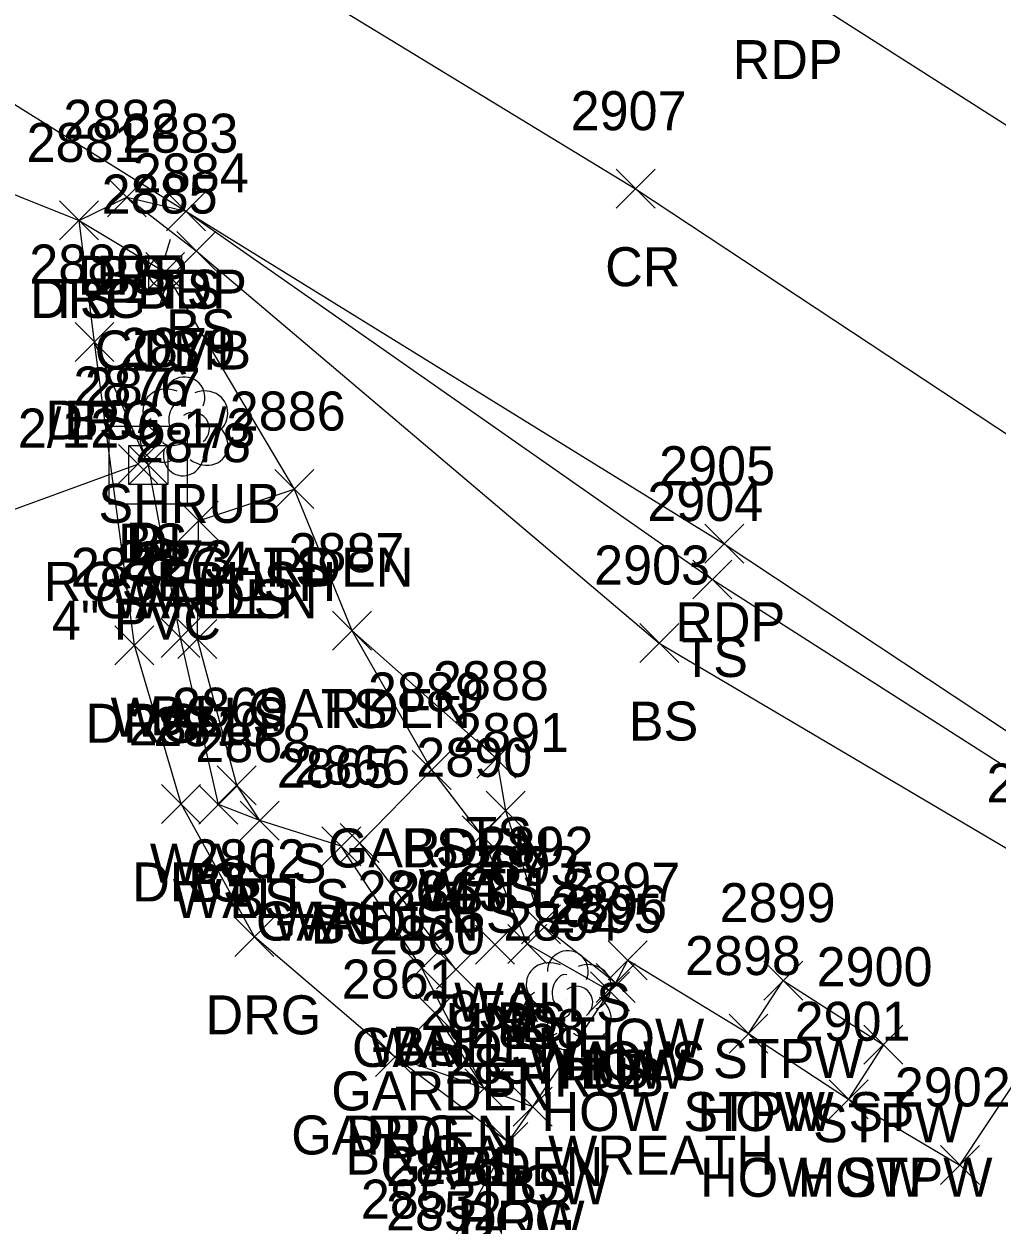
# Model space of a CAD drawing. Extents: x 1499292 to 1501024, y 534584 to 538043.
# Drawn here: x 1499668.2 to 1499718.2, y 537733.8 to 537795.2 of the extents above; entities that cross this region are included whole.
import ezdxf

# ---------------------------------------------------------------- set-up
doc = ezdxf.new("R2010")
doc.units = 0
for name, color, linetype in [('D_A', 7, 'Continuous'), ('D_C', 7, 'Continuous'), ('D_I', 7, 'Continuous'), ('D_TIC', 7, 'Continuous'), ('DCP', 7, 'Continuous'), ('DS', 7, 'Continuous'), ('L_A', 7, 'Continuous'), ('L_C', 7, 'Continuous'), ('L_I', 7, 'Continuous'), ('L_TIC', 7, 'Continuous'), ('LAPB', 7, 'Continuous'), ('LBC', 7, 'Continuous'), ('LBF', 7, 'Continuous'), ('LELB', 7, 'Continuous'), ('LSH', 7, 'Continuous'), ('LWS', 7, 'Continuous'), ('P_A', 7, 'Continuous'), ('P_I', 7, 'Continuous'), ('P_TIC', 7, 'Continuous'), ('PET', 7, 'Continuous'), ('PRC', 7, 'Continuous'), ('R_A', 7, 'Continuous'), ('R_I', 7, 'Continuous'), ('R_TIC', 7, 'Continuous'), ('RDG', 7, 'Continuous'), ('RDP', 7, 'Continuous'), ('U_A', 7, 'Continuous'), ('U_C', 7, 'Continuous'), ('U_I', 7, 'Continuous'), ('UP', 7, 'Continuous')]:
    doc.layers.add(name, color=color, linetype=linetype)

msp = doc.modelspace()

# ---------------------------------------------------------------- linework, layer by layer
at = {"layer": 'D_TIC'}
for points in [[(1499673.076, 537771.661), (1499675.076, 537773.661)], [(1499675.076, 537771.661), (1499673.076, 537773.661)], [(1499691.393, 537747.018), (1499693.393, 537749.018)], [(1499693.393, 537747.018), (1499691.393, 537749.018)]]:
    msp.add_lwpolyline(points, dxfattribs=at)
at = {"layer": 'DCP'}
msp.add_lwpolyline([(1499658.416, 537766.949), (1499674.076, 537772.661)], dxfattribs=at)
at = {"layer": 'DS'}
for p, q in [((1499672.605, 537774.607), (1499676.605, 537774.607)), ((1499672.605, 537770.607), (1499672.605, 537774.607)), ((1499676.605, 537774.607), (1499676.605, 537770.607)), ((1499673.605, 537771.607), (1499673.605, 537773.607)), ((1499673.605, 537773.607), (1499675.605, 537773.607)), ((1499675.605, 537773.607), (1499675.605, 537771.607)), ((1499674.61, 537772.609), (1499674.61, 537772.609)), ((1499674.61, 537772.609), (1499674.61, 537772.609)), ((1499675.605, 537771.607), (1499673.605, 537771.607)), ((1499676.605, 537770.607), (1499672.605, 537770.607))]:
    msp.add_line(p, q, dxfattribs=at)
at = {"layer": 'L_TIC'}
for points in [[(1499672.505, 537785.342), (1499674.505, 537787.342)], [(1499674.505, 537785.342), (1499672.505, 537787.342)], [(1499675.536, 537784.628), (1499677.536, 537786.628)], [(1499677.536, 537784.628), (1499675.536, 537786.628)], [(1499670.052, 537784.153), (1499672.052, 537786.153)], [(1499672.052, 537784.153), (1499670.052, 537786.153)], [(1499676.07, 537782.592), (1499678.07, 537784.592)], [(1499678.07, 537782.592), (1499676.07, 537784.592)], [(1499674.472, 537781.508), (1499676.472, 537783.508)], [(1499676.472, 537781.508), (1499674.472, 537783.508)], [(1499670.846, 537777.917), (1499672.846, 537779.917)], [(1499672.846, 537777.917), (1499670.846, 537779.917)], [(1499673.61, 537771.609), (1499675.61, 537773.609)], [(1499675.61, 537771.609), (1499673.61, 537773.609)], [(1499681.099, 537770.379), (1499683.099, 537772.379)], [(1499683.099, 537770.379), (1499681.099, 537772.379)], [(1499681.099, 537770.379), (1499683.099, 537772.379)], [(1499683.099, 537770.379), (1499681.099, 537772.379)], [(1499676.189, 537768.757), (1499678.189, 537770.757)], [(1499678.189, 537768.757), (1499676.189, 537770.757)], [(1499676.189, 537768.757), (1499678.189, 537770.757)], [(1499678.189, 537768.757), (1499676.189, 537770.757)], [(1499702.551, 537765.74), (1499704.551, 537767.74)], [(1499704.551, 537765.74), (1499702.551, 537767.74)], [(1499684.056, 537763.119), (1499686.056, 537765.119)], [(1499686.056, 537763.119), (1499684.056, 537765.119)], [(1499684.056, 537763.119), (1499686.056, 537765.119)], [(1499686.056, 537763.119), (1499684.056, 537765.119)], [(1499675.259, 537762.746), (1499677.259, 537764.746)], [(1499677.259, 537762.746), (1499675.259, 537764.746)], [(1499676.126, 537762.686), (1499678.126, 537764.686)], [(1499678.126, 537762.686), (1499676.126, 537764.686)], [(1499699.821, 537762.481), (1499701.821, 537764.481)], [(1499701.821, 537762.481), (1499699.821, 537764.481)], [(1499691.471, 537756.552), (1499693.471, 537758.552)], [(1499693.471, 537756.552), (1499691.471, 537758.552)], [(1499688.144, 537755.971), (1499690.144, 537757.971)], [(1499690.144, 537755.971), (1499688.144, 537757.971)], [(1499688.144, 537755.971), (1499690.144, 537757.971)], [(1499690.144, 537755.971), (1499688.144, 537757.971)], [(1499688.144, 537755.971), (1499690.144, 537757.971)], [(1499690.144, 537755.971), (1499688.144, 537757.971)], [(1499678.143, 537755.19), (1499680.143, 537757.19)], [(1499680.143, 537755.19), (1499678.143, 537757.19)], [(1499677.208, 537754.193), (1499679.208, 537756.193)], [(1499679.208, 537754.193), (1499677.208, 537756.193)], [(1499691.938, 537753.891), (1499693.938, 537755.891)], [(1499693.938, 537753.891), (1499691.938, 537755.891)], [(1499691.938, 537753.891), (1499693.938, 537755.891)], [(1499693.938, 537753.891), (1499691.938, 537755.891)], [(1499679.323, 537753.372), (1499681.323, 537755.372)], [(1499681.323, 537753.372), (1499679.323, 537755.372)], [(1499679.323, 537753.372), (1499681.323, 537755.372)], [(1499681.323, 537753.372), (1499679.323, 537755.372)], [(1499690.705, 537752.622), (1499692.705, 537754.622)], [(1499692.705, 537752.622), (1499690.705, 537754.622)], [(1499683.508, 537752.062), (1499685.508, 537754.062)], [(1499685.508, 537752.062), (1499683.508, 537754.062)], [(1499684.457, 537752.222), (1499686.457, 537754.222)], [(1499686.457, 537752.222), (1499684.457, 537754.222)], [(1499684.457, 537752.222), (1499686.457, 537754.222)], [(1499686.457, 537752.222), (1499684.457, 537754.222)], [(1499693.76, 537748.06), (1499695.76, 537750.06)], [(1499695.76, 537748.06), (1499693.76, 537750.06)], [(1499693.048, 537747.054), (1499695.048, 537749.054)], [(1499695.048, 537747.054), (1499693.048, 537749.054)], [(1499698.211, 537746.217), (1499700.211, 537748.217)], [(1499700.211, 537746.217), (1499698.211, 537748.217)], [(1499687.651, 537745.809), (1499689.651, 537747.809)], [(1499689.651, 537745.809), (1499687.651, 537747.809)], [(1499689.388, 537745.741), (1499691.388, 537747.741)], [(1499691.388, 537745.741), (1499689.388, 537747.741)], [(1499689.388, 537745.741), (1499691.388, 537747.741)], [(1499691.388, 537745.741), (1499689.388, 537747.741)], [(1499697.593, 537745.054), (1499699.593, 537747.054)], [(1499699.593, 537745.054), (1499697.593, 537747.054)], [(1499697.593, 537745.054), (1499699.593, 537747.054)], [(1499699.593, 537745.054), (1499697.593, 537747.054)], [(1499706.188, 537745.17), (1499708.188, 537747.17)], [(1499708.188, 537745.17), (1499706.188, 537747.17)], [(1499697.305, 537744.626), (1499699.305, 537746.626)], [(1499699.305, 537744.626), (1499697.305, 537746.626)], [(1499697.305, 537744.626), (1499699.305, 537746.626)], [(1499699.305, 537744.626), (1499697.305, 537746.626)], [(1499688.325, 537743.511), (1499690.325, 537745.511)], [(1499690.325, 537743.511), (1499688.325, 537745.511)], [(1499704.404, 537742.454), (1499706.404, 537744.454)], [(1499706.404, 537742.454), (1499704.404, 537744.454)], [(1499704.404, 537742.454), (1499706.404, 537744.454)], [(1499706.404, 537742.454), (1499704.404, 537744.454)], [(1499711.324, 537741.883), (1499713.324, 537743.883)], [(1499713.324, 537741.883), (1499711.324, 537743.883)], [(1499686.27, 537741.251), (1499688.27, 537743.251)], [(1499688.27, 537741.251), (1499686.27, 537743.251)], [(1499690.846, 537739.643), (1499692.846, 537741.643)], [(1499692.846, 537739.643), (1499690.846, 537741.643)], [(1499690.846, 537739.643), (1499692.846, 537741.643)], [(1499692.846, 537739.643), (1499690.846, 537741.643)], [(1499690.846, 537739.643), (1499692.846, 537741.643)], [(1499692.846, 537739.643), (1499690.846, 537741.643)], [(1499709.54, 537739.083), (1499711.54, 537741.083)], [(1499711.54, 537739.083), (1499709.54, 537741.083)], [(1499709.54, 537739.083), (1499711.54, 537741.083)], [(1499711.54, 537739.083), (1499709.54, 537741.083)], [(1499693.333, 537738.703), (1499695.333, 537740.703)], [(1499695.333, 537738.703), (1499693.333, 537740.703)], [(1499693.333, 537738.703), (1499695.333, 537740.703)], [(1499695.333, 537738.703), (1499693.333, 537740.703)], [(1499692.073, 537736.884), (1499694.073, 537738.884)], [(1499694.073, 537736.884), (1499692.073, 537738.884)], [(1499715.249, 537735.711), (1499717.249, 537737.711)], [(1499717.249, 537735.711), (1499715.249, 537737.711)]]:
    msp.add_lwpolyline(points, dxfattribs=at)
at = {"layer": 'LAPB'}
for points in [[(1499677.189, 537769.757), (1499682.099, 537771.379), (1499685.056, 537764.119), (1499689.144, 537756.971)], [(1499685.457, 537753.222), (1499689.144, 537756.971)], [(1499691.846, 537740.643), (1499689.325, 537744.511)], [(1499691.846, 537740.643), (1499687.27, 537742.251)]]:
    msp.add_lwpolyline(points, dxfattribs=at)
at = {"layer": 'LBC'}
msp.add_lwpolyline([(1499697.587, 537727.89), (1499690.115, 537732.638), (1499693.073, 537737.884), (1499694.333, 537739.703), (1499698.305, 537745.626), (1499698.593, 537746.054), (1499699.211, 537747.217), (1499705.404, 537743.454), (1499710.54, 537740.083), (1499716.249, 537736.711), (1499721.755, 537744.999), (1499738.986, 537733.643), (1499732.104, 537722.822), (1499729.121, 537718.079), (1499724.689, 537711.282), (1499721.272, 537713.245)], dxfattribs=at)
at = {"layer": 'LBF'}
msp.add_lwpolyline([(1499705.404, 537743.454), (1499707.188, 537746.17), (1499712.324, 537742.883), (1499710.54, 537740.083)], dxfattribs=at)
at = {"layer": 'LELB'}
for points in [[(1499673.505, 537786.342), (1499677.07, 537783.592), (1499700.821, 537763.481), (1499719.743, 537752.304), (1499723.657, 537747.33), (1499740.89, 537735.965), (1499752.712, 537719.821), (1499760.138, 537714.193), (1499776.543, 537702.52), (1499783.898, 537695.878)], [(1499671.052, 537785.153), (1499675.472, 537782.508), (1499682.099, 537771.379)], [(1499676.536, 537785.628), (1499703.551, 537766.74), (1499721.632, 537755.195), (1499743.729, 537738.33)], [(1499694.333, 537739.703), (1499691.846, 537740.643), (1499688.651, 537746.809), (1499684.508, 537753.062), (1499680.323, 537754.372), (1499678.208, 537755.193), (1499676.259, 537763.746), (1499674.61, 537772.609), (1499671.846, 537778.917)], [(1499685.056, 537764.119), (1499692.471, 537757.552), (1499692.938, 537754.891)], [(1499689.144, 537756.971), (1499691.705, 537753.622), (1499694.048, 537748.054), (1499698.305, 537745.626)]]:
    msp.add_lwpolyline(points, dxfattribs=at)
at = {"layer": 'LSH'}
for p, q in [((1499676.416, 537774.644), (1499676.416, 537774.644)), ((1499676.416, 537774.644), (1499676.416, 537774.644)), ((1499696.087, 537745.221), (1499696.087, 537745.221)), ((1499696.087, 537745.221), (1499696.087, 537745.221))]:
    msp.add_line(p, q, dxfattribs=at)
for centre in [(1499676.463, 537776.078), (1499696.134, 537746.655)]:
    msp.add_arc(centre, 1.047, 335.52715, 180.95627, dxfattribs=at)
for centre, major_axis, ratio, start_param, end_param in [((1499675.624, 537775.31), (1.21, -0.512), 0.895232, 1.570796, 4.712389), ((1499677.458, 537775.227), (-1.141, -0.483), 0.949671, 1.570796, 4.712389), ((1499676.208, 537775.102), (-0.208, -0.792), 0.645439, 3.141593, 6.283185), ((1499676.916, 537774.477), (-0.5, 0.667), 0.989748, 3.141593, 6.283185), ((1499675.333, 537773.935), (0.584, -1.042), 0.959034, 3.141593, 6.283185), ((1499677.416, 537773.811), (-1.09, 0.792), 0.841452, 1.570796, 4.712389), ((1499676.416, 537773.144), (0.265, 1.061), 0.942809, 1.570796, 4.712389), ((1499675.958, 537773.894), (-0.625, -0.083), 0.423636, 0, 3.141593), ((1499695.295, 537745.887), (1.21, -0.512), 0.895232, 1.570796, 4.712389), ((1499697.129, 537745.804), (-1.141, -0.483), 0.949671, 1.570796, 4.712389), ((1499695.879, 537745.679), (-0.208, -0.792), 0.645439, 3.141593, 6.283185), ((1499696.587, 537745.054), (-0.5, 0.667), 0.989748, 3.141593, 6.283185), ((1499695.004, 537744.512), (0.584, -1.042), 0.959034, 3.141593, 6.283185), ((1499697.087, 537744.388), (-1.09, 0.792), 0.841452, 1.570796, 4.712389), ((1499695.629, 537744.471), (-0.625, -0.083), 0.423636, 0, 3.141593), ((1499696.087, 537743.721), (0.265, 1.061), 0.942809, 1.570796, 4.712389)]:
    msp.add_ellipse(centre, major_axis=major_axis, ratio=ratio, start_param=start_param, end_param=end_param, dxfattribs=at)
at = {"layer": 'LWS'}
for points in [[(1499680.323, 537754.372), (1499679.143, 537756.19), (1499677.126, 537763.686), (1499677.189, 537769.757)], [(1499692.938, 537754.891), (1499694.76, 537749.06), (1499698.593, 537746.054)], [(1499690.388, 537746.741), (1499685.457, 537753.222)]]:
    msp.add_lwpolyline(points, dxfattribs=at)
at = {"layer": 'P_TIC'}
for points in [[(1499698.614, 537785.782), (1499700.614, 537787.782)], [(1499700.614, 537785.782), (1499698.614, 537787.782)], [(1499675.536, 537784.628), (1499677.536, 537786.628)], [(1499677.536, 537784.628), (1499675.536, 537786.628)], [(1499703.158, 537767.574), (1499705.158, 537769.574)], [(1499705.158, 537767.574), (1499703.158, 537769.574)]]:
    msp.add_lwpolyline(points, dxfattribs=at)
at = {"layer": 'PET'}
for points in [[(1499318.777, 538007.185), (1499356.077, 537991.329), (1499396.207, 537971.039), (1499437.012, 537950.167), (1499476.074, 537929.172), (1499509.306, 537910.677), (1499546.423, 537890.59), (1499566.293, 537879.272), (1499602.082, 537858.76), (1499615.195, 537851.418), (1499643.027, 537835.063), (1499676.234, 537815.623), (1499707.101, 537797.403), (1499725.198, 537785.865), (1499749.466, 537768.587), (1499768.247, 537754.161), (1499782.48, 537740.777), (1499805.279, 537716.472), (1499820.533, 537699.08)], [(1499310.023, 537983.746), (1499343.075, 537969.541), (1499383.731, 537949.439), (1499427.71, 537927.425), (1499464.171, 537907.983), (1499500.199, 537887.497), (1499544.495, 537863.142), (1499587.74, 537838.677), (1499616.247, 537822.183), (1499651.021, 537801.554), (1499676.536, 537785.628), (1499704.158, 537768.574), (1499722.55, 537756.398), (1499745.414, 537739.8), (1499767.298, 537722.36), (1499790.892, 537701.646), (1499806.057, 537686.036), (1499813.912, 537693.068), (1499820.533, 537699.08)]]:
    msp.add_lwpolyline(points, dxfattribs=at)
at = {"layer": 'PRC'}
msp.add_lwpolyline([(1499314.647, 537995.238), (1499351.896, 537980.059), (1499390.853, 537960.785), (1499432.771, 537938.063), (1499470.255, 537918.917), (1499503.529, 537899.736), (1499550.301, 537873.589), (1499594.281, 537849.334), (1499631.071, 537828.01), (1499665.93, 537807.267), (1499699.614, 537786.782), (1499728.317, 537767.815), (1499774.937, 537731.181), (1499796.918, 537710.716), (1499813.912, 537693.068)], dxfattribs=at)
at = {"layer": 'R_TIC'}
for points in [[(1499672.505, 537785.342), (1499674.505, 537787.342)], [(1499674.505, 537785.342), (1499672.505, 537787.342)], [(1499675.536, 537784.628), (1499677.536, 537786.628)], [(1499677.536, 537784.628), (1499675.536, 537786.628)], [(1499670.052, 537784.153), (1499672.052, 537786.153)], [(1499672.052, 537784.153), (1499670.052, 537786.153)], [(1499670.052, 537784.153), (1499672.052, 537786.153)], [(1499672.052, 537784.153), (1499670.052, 537786.153)], [(1499670.846, 537777.917), (1499672.846, 537779.917)], [(1499672.846, 537777.917), (1499670.846, 537779.917)], [(1499672.894, 537762.367), (1499674.894, 537764.367)], [(1499674.894, 537762.367), (1499672.894, 537764.367)], [(1499675.292, 537754.227), (1499677.292, 537756.227)], [(1499677.292, 537754.227), (1499675.292, 537756.227)], [(1499679.055, 537747.413), (1499681.055, 537749.413)], [(1499681.055, 537747.413), (1499679.055, 537749.413)], [(1499686.27, 537741.251), (1499688.27, 537743.251)], [(1499688.27, 537741.251), (1499686.27, 537743.251)], [(1499692.073, 537736.884), (1499694.073, 537738.884)], [(1499694.073, 537736.884), (1499692.073, 537738.884)]]:
    msp.add_lwpolyline(points, dxfattribs=at)
at = {"layer": 'RDG'}
msp.add_lwpolyline([(1499693.073, 537737.884), (1499687.27, 537742.251), (1499680.055, 537748.413), (1499676.292, 537755.227), (1499673.894, 537763.367), (1499671.846, 537778.917), (1499671.052, 537785.153)], dxfattribs=at)
at = {"layer": 'RDP'}
msp.add_lwpolyline([(1499651.021, 537801.554), (1499653.673, 537795.813), (1499661.704, 537788.897), (1499671.052, 537785.153), (1499673.505, 537786.342), (1499676.536, 537785.628)], dxfattribs=at)
at = {"layer": 'UP'}
for p, q in [((1499675.722, 537784.175), (1499675.472, 537783.341)), ((1499674.639, 537781.675), (1499674.639, 537783.341)), ((1499674.639, 537783.341), (1499676.306, 537783.341)), ((1499676.306, 537783.341), (1499676.306, 537781.675)), ((1499675.472, 537782.508), (1499675.472, 537782.508)), ((1499676.306, 537781.675), (1499674.639, 537781.675)), ((1499675.222, 537780.841), (1499675.472, 537781.675))]:
    msp.add_line(p, q, dxfattribs=at)
msp.add_circle((1499675.472, 537782.508), 0.833, dxfattribs=at)

# ---------------------------------------------------------------- texts
at = {"layer": 'D_A'}
for s, p in [('P', (1499673.453, 537767.661)), ('DI', (1499673.665, 537767.609)), ('UND', (1499689.865, 537743.018))]:
    msp.add_text(s, height=2, dxfattribs=at).set_placement(p)
at = {"layer": 'D_C'}
msp.add_text('4" PVC', height=2, dxfattribs=at).set_placement((1499669.658, 537763.661))
at = {"layer": 'D_I'}
for s, p in [('2876', (1499670.761, 537775.661)), ('2877', (1499671.35, 537775.609)), ('2867', (1499689.086, 537751.018))]:
    msp.add_text(s, height=2, dxfattribs=at).set_placement(p)
at = {"layer": 'L_A'}
for s, p in [('BS', (1499671.946, 537781.342)), ('TS', (1499674.946, 537780.628)), ('TS', (1499669.461, 537780.153)), ('BS', (1499675.511, 537778.592)), ('TS', (1499673.882, 537777.508)), ('BS', (1499670.287, 537773.917)), ('SHRUB', (1499672.046, 537769.644)), ('BS', (1499673.051, 537767.609)), ('GARDEN', (1499676.769, 537766.379)), ('TS', (1499680.509, 537766.379)), ('GARDEN', (1499671.858, 537764.757)), ('WALLS', (1499672.732, 537764.757)), ('TS', (1499701.961, 537761.74)), ('GARDEN', (1499679.725, 537759.119)), ('TS', (1499683.465, 537759.119)), ('WALLS', (1499672.67, 537758.686)), ('BS', (1499674.7, 537758.746)), ('BS', (1499699.262, 537758.481)), ('TS', (1499690.88, 537752.552)), ('GARDEN', (1499683.813, 537751.971)), ('GARDEN', (1499683.813, 537751.971)), ('BS', (1499687.585, 537751.971)), ('WALLS', (1499674.686, 537751.19)), ('BS', (1499676.649, 537750.193)), ('WALLS', (1499688.482, 537749.891)), ('TS', (1499691.348, 537749.891)), ('WALLS', (1499675.866, 537749.372)), ('BS', (1499678.764, 537749.372)), ('GARDEN', (1499680.126, 537748.222)), ('WALLS', (1499681, 537748.222)), ('BS', (1499682.949, 537748.062)), ('BS', (1499690.146, 537748.622)), ('WALLS', (1499690.304, 537744.06)), ('BS', (1499692.489, 537743.054)), ('HOW', (1499696.597, 537742.217)), ('GARDEN', (1499685.058, 537741.741)), ('WALLS', (1499685.932, 537741.741)), ('BS', (1499687.092, 537741.809)), ('WALLS', (1499694.137, 537741.054)), ('HOW', (1499695.979, 537741.054)), ('STPW', (1499703.582, 537741.17)), ('SHRUB', (1499691.717, 537740.221)), ('HOW', (1499695.691, 537740.626)), ('BS', (1499696.746, 537740.626)), ('GARDEN', (1499683.995, 537739.511)), ('HOW STPW ST', (1499694.782, 537738.454)), ('HOW', (1499702.79, 537738.454)), ('STPW', (1499708.718, 537737.883)), ('GARDEN', (1499681.939, 537737.251)), ('GARDEN', (1499686.515, 537735.643)), ('GARDEN', (1499686.515, 537735.643)), ('BS', (1499690.287, 537735.643)), ('HOW', (1499691.719, 537734.703)), ('BS', (1499692.774, 537734.703)), ('HOW STPW', (1499702.918, 537735.083)), ('HOW', (1499707.926, 537735.083)), ('HOW', (1499690.459, 537732.884))]:
    msp.add_text(s, height=2, dxfattribs=at).set_placement(p)
at = {"layer": 'L_C'}
for s, p in [('ROSEBUSH', (1499669.235, 537765.644)), ('BRIDAL WREATH', (1499684.717, 537736.221))]:
    msp.add_text(s, height=2, dxfattribs=at).set_placement(p)
at = {"layer": 'L_I'}
for s, p in [('2882', (1499670.245, 537789.342)), ('2883', (1499673.276, 537788.628)), ('2881', (1499668.359, 537788.153)), ('2884', (1499673.811, 537786.592)), ('2885', (1499672.213, 537785.508)), ('2880', (1499668.5, 537781.917)), ('2879', (1499673.148, 537777.644)), ('2877', (1499671.35, 537775.609)), ('2886', (1499678.785, 537774.379)), ('2886', (1499678.785, 537774.379)), ('2878', (1499673.929, 537772.757)), ('2878', (1499673.929, 537772.757)), ('2904', (1499700.213, 537769.74)), ('2887', (1499681.796, 537767.119)), ('2887', (1499681.796, 537767.119)), ('2873', (1499672.999, 537766.746)), ('2874', (1499673.866, 537766.686)), ('2903', (1499697.483, 537766.481)), ('2888', (1499689.211, 537760.552)), ('2889', (1499685.876, 537759.971)), ('2889', (1499685.876, 537759.971)), ('2889', (1499685.876, 537759.971)), ('2869', (1499675.828, 537759.19)), ('2870', (1499674.861, 537758.193)), ('2891', (1499690.245, 537757.891)), ('2891', (1499690.245, 537757.891)), ('2868', (1499677.016, 537757.372)), ('2868', (1499677.016, 537757.372)), ('2890', (1499688.358, 537756.622)), ('2865', (1499681.201, 537756.062)), ('2866', (1499682.094, 537756.222)), ('2866', (1499682.094, 537756.222)), ('2911', (1499717.617, 537755.304)), ('2892', (1499691.5, 537752.06)), ('2893', (1499690.788, 537751.054)), ('2897', (1499695.951, 537750.217)), ('2864', (1499685.344, 537749.809)), ('2863', (1499687.081, 537749.741)), ('2863', (1499687.081, 537749.741)), ('2896', (1499695.278, 537749.054)), ('2896', (1499695.278, 537749.054)), ('2899', (1499703.92, 537749.17)), ('2894', (1499692.827, 537748.221)), ('2895', (1499695.045, 537748.626)), ('2895', (1499695.045, 537748.626)), ('2860', (1499685.932, 537747.511)), ('2898', (1499702.144, 537746.454)), ('2898', (1499702.144, 537746.454)), ('2900', (1499708.899, 537745.883)), ('2861', (1499684.53, 537745.251)), ('2859', (1499688.578, 537743.643)), ('2859', (1499688.578, 537743.643)), ('2859', (1499688.578, 537743.643)), ('2858', (1499691.073, 537742.703)), ('2858', (1499691.073, 537742.703)), ('2901', (1499707.769, 537743.083)), ('2901', (1499707.769, 537743.083)), ('2857', (1499689.813, 537740.884)), ('2902', (1499712.91, 537739.711)), ('2856', (1499686.8, 537735.638)), ('2852', (1499686.8, 537733.355))]:
    msp.add_text(s, height=2, dxfattribs=at).set_placement(p)
at = {"layer": 'P_A'}
for s, p in [('RDP', (1499704.59, 537792.403)), ('CR', (1499698.048, 537781.782)), ('RDP', (1499674.024, 537780.628)), ('RDP', (1499701.646, 537763.574))]:
    msp.add_text(s, height=2, dxfattribs=at).set_placement(p)
at = {"layer": 'P_I'}
for s, p in [('2907', (1499696.276, 537789.782)), ('2883', (1499673.276, 537788.628)), ('2905', (1499700.819, 537771.574))]:
    msp.add_text(s, height=2, dxfattribs=at).set_placement(p)
at = {"layer": 'R_A'}
for s, p in [('DRP', (1499670.993, 537781.342)), ('DRP', (1499674.024, 537780.628)), ('DRG', (1499668.54, 537780.153)), ('DRP', (1499668.54, 537780.153)), ('DRG', (1499669.335, 537773.917)), ('DRG', (1499671.383, 537758.367)), ('DRG', (1499673.78, 537750.227)), ('DRG', (1499677.543, 537743.413)), ('DRG', (1499684.758, 537737.251)), ('DRG', (1499690.561, 537732.884))]:
    msp.add_text(s, height=2, dxfattribs=at).set_placement(p)
at = {"layer": 'R_I'}
for s, p in [('2882', (1499670.245, 537789.342)), ('2883', (1499673.276, 537788.628)), ('2881', (1499668.359, 537788.153)), ('2881', (1499668.359, 537788.153)), ('2880', (1499668.5, 537781.917)), ('2872', (1499670.634, 537766.367)), ('2871', (1499673.599, 537758.227)), ('2862', (1499676.748, 537751.413)), ('2861', (1499684.53, 537745.251)), ('2857', (1499689.813, 537740.884)), ('2856', (1499686.8, 537735.638)), ('2853', (1499685.514, 537733.963)), ('2852', (1499686.8, 537733.355))]:
    msp.add_text(s, height=2, dxfattribs=at).set_placement(p)
at = {"layer": 'U_A'}
msp.add_text('COMB', height=2, dxfattribs=at).set_placement((1499671.858, 537777.508))
at = {"layer": 'U_C'}
msp.add_text('2/12-6-1/3', height=2, dxfattribs=at).set_placement((1499667.913, 537773.508))
at = {"layer": 'U_I'}
msp.add_text('2885', height=2, dxfattribs=at).set_placement((1499672.213, 537785.508))

doc.saveas('drawing.dxf')
